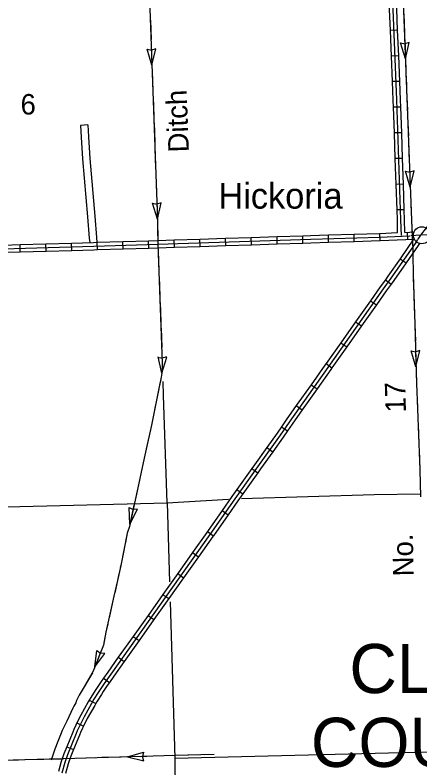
# Model space of a CAD drawing. Extents: x -5566 to 1759129, y -3726 to 731467.
# Drawn here: x -4880.9 to -4817.8, y 389.7 to 507.2 of the extents above; entities that cross this region are included whole.
import ezdxf

# ---------------------------------------------------------------- set-up
doc = ezdxf.new("R2010")
doc.units = 0
doc.layers.add('Default', color=7, linetype='Continuous')

msp = doc.modelspace()

# ---------------------------------------------------------------- linework, layer by layer
at = {"layer": 'Default'}
for p, q in [((-4821.23, 504.86), (-4822.37, 504.81)), ((-4859.56, 499.37), (-4860.33, 501.87)), ((-4860.33, 501.87), (-4859.65, 501.71)), ((-4858.98, 501.91), (-4859.64, 501.71)), ((-4859.56, 499.37), (-4858.98, 501.91)), ((-4820.02, 500.38), (-4820.79, 502.87)), ((-4820.79, 502.87), (-4820.11, 502.72)), ((-4819.44, 502.92), (-4820.1, 502.72)), ((-4820.02, 500.38), (-4819.44, 502.92)), ((-4821.06, 500.85), (-4822.2, 500.8)), ((-4820.9, 496.85), (-4822.03, 496.8)), ((-4820.74, 492.84), (-4821.88, 492.8)), ((-4820.6, 488.83), (-4821.74, 488.79)), ((-4820.47, 484.82), (-4821.6, 484.78)), ((-4819.26, 480.35), (-4820.03, 482.84)), ((-4820.03, 482.84), (-4819.35, 482.68)), ((-4818.68, 482.89), (-4819.34, 482.68)), ((-4819.26, 480.35), (-4818.68, 482.89)), ((-4820.33, 480.81), (-4821.47, 480.77)), ((-4858.71, 475.33), (-4859.47, 477.82)), ((-4859.47, 477.82), (-4858.79, 477.67)), ((-4858.12, 477.87), (-4858.79, 477.67)), ((-4858.71, 475.33), (-4858.12, 477.87)), ((-4820.19, 476.81), (-4821.33, 476.77)), ((-4844.02, 471.34), (-4844.06, 472.48)), ((-4840.02, 471.48), (-4840.05, 472.61)), ((-4836.01, 471.61), (-4836.05, 472.75)), ((-4832, 471.73), (-4832.04, 472.87)), ((-4827.99, 471.86), (-4828.03, 473)), ((-4823.98, 471.98), (-4824.03, 473.12)), ((-4819.63, 472.16), (-4819.68, 473.3)), ((-4880.1, 470.23), (-4880.13, 471.36)), ((-4876.09, 470.34), (-4876.12, 471.48)), ((-4872.08, 470.46), (-4872.11, 471.6)), ((-4868.07, 470.58), (-4868.11, 471.72)), ((-4864.06, 470.7), (-4864.1, 471.84)), ((-4860.06, 470.82), (-4860.09, 471.96)), ((-4856.05, 470.95), (-4856.08, 472.09)), ((-4852.04, 471.08), (-4852.08, 472.22)), ((-4848.03, 471.21), (-4848.07, 472.35)), ((-4820.86, 469.15), (-4819.92, 468.51)), ((-4823.15, 465.88), (-4822.22, 465.21)), ((-4825.48, 462.61), (-4824.55, 461.95)), ((-4827.79, 459.33), (-4826.86, 458.67)), ((-4830.1, 456.05), (-4829.17, 455.4)), ((-4817.76, 454.83), (-4818.42, 454.63)), ((-4818.37, 452.3), (-4817.76, 454.83)), ((-4858.66, 453.78), (-4857.98, 453.62)), ((-4858.01, 451.29), (-4858.59, 453.83)), ((-4858.01, 451.29), (-4857.24, 453.78)), ((-4857.31, 453.83), (-4857.97, 453.62)), ((-4818.37, 452.3), (-4819.11, 454.8)), ((-4819.11, 454.8), (-4818.43, 454.63)), ((-4832.41, 452.78), (-4831.48, 452.12)), ((-4834.72, 449.5), (-4833.79, 448.84)), ((-4837.04, 446.23), (-4836.11, 445.57)), ((-4839.34, 442.93), (-4838.4, 442.29)), ((-4841.65, 439.67), (-4840.72, 439.01)), ((-4843.98, 436.4), (-4843.05, 435.74)), ((-4846.3, 433.14), (-4845.37, 432.48)), ((-4863, 427.75), (-4863.13, 430.35)), ((-4863.13, 430.35), (-4862.51, 430.04)), ((-4863, 427.75), (-4861.81, 430.07)), ((-4861.81, 430.07), (-4862.5, 430.04)), ((-4848.61, 429.85), (-4847.68, 429.2)), ((-4850.91, 426.57), (-4849.98, 425.91)), ((-4853.23, 423.3), (-4852.3, 422.64)), ((-4855.54, 420.03), (-4854.62, 419.37)), ((-4857.86, 416.76), (-4856.93, 416.1)), ((-4860.18, 413.49), (-4859.25, 412.83)), ((-4862.5, 410.21), (-4861.57, 409.56)), ((-4868.45, 405.43), (-4868.17, 408.02)), ((-4868.17, 408.02), (-4867.61, 407.61)), ((-4868.45, 405.43), (-4866.91, 407.53)), ((-4866.91, 407.53), (-4867.6, 407.6)), ((-4864.82, 406.94), (-4863.89, 406.29)), ((-4867.14, 403.67), (-4866.21, 403.01)), ((-4869.35, 400.24), (-4868.34, 399.71)), ((-4871.26, 396.71), (-4870.25, 396.19)), ((-4872.85, 392.98), (-4871.8, 392.55)), ((-4863.39, 391.4), (-4860.89, 392.14)), ((-4863.39, 391.4), (-4860.85, 390.79)), ((-4860.89, 392.14), (-4861.05, 391.47)), ((-4860.85, 390.79), (-4861.05, 391.46))]:
    msp.add_line(p, q, dxfattribs=at)
for points in [[(-4820.65, 472.78), (-4820.71, 475.23), (-4821.35, 493.95), (-4821.93, 508.07), (-4822.06, 511.53), (-4822.06, 512.62), (-4822.03, 513.56), (-4822, 513.82), (-4821.97, 514.21), (-4821.8, 514.93), (-4821.58, 516.04), (-4821.5, 516.72), (-4821.48, 517.29), (-4821.49, 518.21), (-4822.18, 534.35), (-4822.2, 535.05), (-4822.95, 553.69), (-4823.07, 557.61), (-4823.78, 574.98), (-4824.52, 594.47)], [(-4785.83, 515.93), (-4792.8, 506.87), (-4795.14, 503.86), (-4797.87, 500.25), (-4801.97, 494.91), (-4802.55, 494.18), (-4802.7, 493.91), (-4802.86, 493.61), (-4804.41, 491.37), (-4806.14, 488.91), (-4809.39, 484.4), (-4812.72, 479.57), (-4814.45, 477.18), (-4815.22, 476.03), (-4815.91, 475.13), (-4817.67, 472.82), (-4818.06, 472.22)], [(-4820.46, 512.01), (-4818.96, 472.49), (-4818.91, 471.43), (-4818.86, 470.81), (-4818.87, 469.76), (-4818.83, 466.73), (-4818.54, 458.88), (-4818.31, 449.71), (-4817.77, 436.19), (-4817.67, 431.97)], [(-4859.93, 509.67), (-4858.75, 476.57), (-4858.64, 471.44), (-4857.95, 452.87), (-4857.98, 452), (-4858.03, 451.3), (-4858.12, 450.69), (-4858.43, 449.17), (-4859.31, 444.75), (-4859.64, 443.2), (-4860.67, 438.48), (-4863.09, 427.36), (-4863.41, 426.34)], [(-4822.37, 504.81), (-4822.5, 508.05), (-4822.53, 508.82)], [(-4821.23, 504.86), (-4821.36, 508.1), (-4821.39, 508.86)], [(-4820.29, 507.39), (-4820.17, 504.39)], [(-4859.81, 506.39), (-4859.7, 503.38)], [(-4822.2, 500.8), (-4822.37, 504.81)], [(-4821.06, 500.85), (-4821.23, 504.86)], [(-4820.13, 503.39), (-4820.02, 500.38)], [(-4859.67, 502.38), (-4859.56, 499.37)], [(-4822.03, 496.8), (-4822.2, 500.8)], [(-4820.9, 496.85), (-4821.06, 500.85)], [(-4859.53, 498.37), (-4859.47, 496.87)], [(-4819.98, 499.38), (-4819.93, 497.88)], [(-4819.93, 497.88), (-4819.87, 496.38)], [(-4859.47, 496.87), (-4859.42, 495.37)], [(-4821.88, 492.8), (-4821.92, 493.93), (-4822.03, 496.8)], [(-4820.74, 492.84), (-4820.78, 493.98), (-4820.9, 496.85)], [(-4819.83, 495.37), (-4819.72, 492.37)], [(-4859.38, 494.37), (-4859.28, 491.36)], [(-4821.74, 488.79), (-4821.88, 492.8)], [(-4820.6, 488.83), (-4820.74, 492.84)], [(-4819.68, 491.37), (-4819.56, 488.36)], [(-4859.24, 490.36), (-4859.13, 487.35)], [(-4869.57, 490.05), (-4870.7, 489.98), (-4870.6, 488.11), (-4870.38, 484.73), (-4869.63, 475.69), (-4869.35, 472.38), (-4869.28, 471.68)], [(-4869.57, 490.05), (-4869.46, 488.18), (-4869.24, 484.82), (-4868.49, 475.79), (-4868.21, 472.49), (-4868.14, 471.71)], [(-4821.6, 484.78), (-4821.74, 488.79)], [(-4820.47, 484.82), (-4820.6, 488.83)], [(-4819.53, 487.36), (-4819.41, 484.35)], [(-4859.1, 486.35), (-4858.99, 483.35)], [(-4821.47, 480.77), (-4821.6, 484.78)], [(-4820.33, 480.81), (-4820.47, 484.82)], [(-4819.37, 483.35), (-4819.26, 480.35)], [(-4858.96, 482.34), (-4858.85, 479.34)], [(-4821.33, 476.77), (-4821.47, 480.77)], [(-4820.19, 476.81), (-4820.33, 480.81)], [(-4858.81, 478.34), (-4858.75, 476.57), (-4858.72, 475.33)], [(-4819.22, 479.35), (-4819.11, 476.34)], [(-4821.23, 473.24), (-4821.28, 475.21), (-4821.33, 476.77)], [(-4820.09, 473.28), (-4820.14, 475.24), (-4820.19, 476.81)], [(-4760.09, 474.99), (-4769.7, 474.49), (-4779.76, 474.01), (-4783.25, 473.89), (-4795.37, 473.47), (-4799.28, 473.39), (-4811.13, 473.04), (-4817.67, 472.82), (-4819.19, 472.75)], [(-4819.07, 475.34), (-4819.01, 473.84)], [(-4858.7, 474.33), (-4858.67, 472.82)], [(-4819.01, 473.84), (-4818.99, 473.33)], [(-4858.67, 472.82), (-4858.65, 472.01)], [(-4858.64, 471.44), (-4834.8, 472.22), (-4824.02, 472.55), (-4819.38, 472.74), (-4819.33, 472.75)], [(-4848.07, 472.35), (-4844.06, 472.48)], [(-4844.06, 472.48), (-4840.05, 472.61)], [(-4840.05, 472.61), (-4836.05, 472.75)], [(-4836.05, 472.75), (-4834.82, 472.79), (-4832.04, 472.87)], [(-4832.04, 472.87), (-4828.03, 473)], [(-4828.03, 473), (-4824.04, 473.12), (-4824.03, 473.12)], [(-4824.03, 473.12), (-4821.23, 473.24)], [(-4820.09, 473.28), (-4818.68, 473.34)], [(-4888.25, 470.56), (-4868.65, 471.13), (-4858.64, 471.44)], [(-4884.14, 471.25), (-4880.13, 471.36)], [(-4880.13, 471.36), (-4876.12, 471.48)], [(-4876.12, 471.48), (-4872.11, 471.6)], [(-4872.11, 471.6), (-4868.67, 471.7), (-4868.11, 471.72)], [(-4868.11, 471.72), (-4864.1, 471.84)], [(-4864.1, 471.84), (-4860.09, 471.96)], [(-4860.09, 471.96), (-4858.66, 472.01), (-4856.08, 472.09)], [(-4856.08, 472.09), (-4852.08, 472.22)], [(-4852.08, 472.22), (-4848.07, 472.35)], [(-4818.12, 472.14), (-4818.49, 471.56), (-4822.28, 466.1), (-4823.47, 464.46), (-4832.12, 452.2), (-4838.15, 443.66), (-4839.55, 441.63), (-4843.08, 436.68), (-4846.62, 431.7), (-4850.54, 426.11)], [(-4848.03, 471.21), (-4844.02, 471.34)], [(-4844.02, 471.34), (-4840.02, 471.48)], [(-4840.02, 471.48), (-4836.01, 471.61)], [(-4836.01, 471.61), (-4834.78, 471.65), (-4832, 471.73)], [(-4832, 471.73), (-4827.99, 471.86)], [(-4827.99, 471.86), (-4824, 471.98), (-4823.98, 471.98)], [(-4823.98, 471.98), (-4819.97, 472.15)], [(-4818.74, 472.2), (-4820.86, 469.15)], [(-4819.97, 472.15), (-4818.74, 472.2)], [(-4817.82, 471.55), (-4818.02, 471.24), (-4819.92, 468.51)], [(-4884.1, 470.11), (-4880.1, 470.23)], [(-4880.1, 470.23), (-4876.09, 470.34)], [(-4876.09, 470.34), (-4872.08, 470.46)], [(-4872.08, 470.46), (-4868.63, 470.56), (-4868.07, 470.58)], [(-4868.07, 470.58), (-4864.06, 470.7)], [(-4864.06, 470.7), (-4860.06, 470.82)], [(-4860.06, 470.82), (-4858.62, 470.87), (-4856.05, 470.95)], [(-4858.6, 470.32), (-4858.48, 467.31)], [(-4856.05, 470.95), (-4852.04, 471.08)], [(-4852.04, 471.08), (-4848.03, 471.21)], [(-4820.86, 469.15), (-4822.74, 466.43), (-4823.15, 465.88)], [(-4818.87, 470.02), (-4818.85, 468.33)], [(-4819.92, 468.51), (-4821.81, 465.77), (-4822.22, 465.21)], [(-4818.83, 467.33), (-4818.83, 466.73), (-4818.74, 464.32)], [(-4858.45, 466.31), (-4858.34, 463.31)], [(-4823.15, 465.88), (-4823.94, 464.79), (-4825.48, 462.61)], [(-4822.22, 465.21), (-4823.01, 464.13), (-4824.55, 461.95)], [(-4818.7, 463.32), (-4818.59, 460.31)], [(-4858.3, 462.31), (-4858.19, 459.3)], [(-4825.48, 462.61), (-4827.79, 459.33)], [(-4824.55, 461.95), (-4826.86, 458.67)], [(-4827.79, 459.33), (-4830.1, 456.05)], [(-4826.86, 458.67), (-4829.17, 455.4)], [(-4818.55, 459.31), (-4818.54, 458.88), (-4818.47, 456.31)], [(-4858.15, 458.3), (-4858.04, 455.29)], [(-4830.1, 456.05), (-4832.41, 452.78)], [(-4829.17, 455.4), (-4831.48, 452.12)], [(-4818.45, 455.3), (-4818.37, 452.3)], [(-4858, 454.29), (-4857.95, 452.87), (-4857.98, 452), (-4858.03, 451.3), (-4858.03, 451.29)], [(-4832.41, 452.78), (-4832.58, 452.53), (-4834.72, 449.5)], [(-4831.48, 452.12), (-4831.65, 451.87), (-4833.79, 448.84)], [(-4818.35, 451.29), (-4818.31, 449.79)], [(-4858.2, 450.3), (-4858.43, 449.17), (-4858.5, 448.83)], [(-4857.17, 431.08), (-4857.77, 447.81), (-4857.83, 450.01)], [(-4834.72, 449.5), (-4837.04, 446.23)], [(-4818.31, 449.79), (-4818.31, 449.71), (-4818.25, 448.29)], [(-4858.5, 448.83), (-4858.79, 447.35)], [(-4833.79, 448.84), (-4836.11, 445.57)], [(-4818.21, 447.29), (-4818.09, 444.28)], [(-4858.99, 446.37), (-4859.31, 444.75), (-4859.6, 443.42)], [(-4837.04, 446.23), (-4838.62, 443.99), (-4839.34, 442.93)], [(-4836.11, 445.57), (-4837.68, 443.34), (-4838.4, 442.29)], [(-4818.05, 443.28), (-4817.93, 440.28)], [(-4859.81, 442.44), (-4860.45, 439.51)], [(-4839.34, 442.93), (-4840.01, 441.95), (-4841.65, 439.67)], [(-4838.4, 442.29), (-4839.08, 441.3), (-4840.72, 439.01)], [(-4841.65, 439.67), (-4843.55, 437.01), (-4843.98, 436.4)], [(-4860.66, 438.53), (-4860.67, 438.48), (-4861.3, 435.59)], [(-4840.72, 439.01), (-4842.62, 436.35), (-4843.05, 435.74)], [(-4817.9, 439.27), (-4817.78, 436.27)], [(-4843.98, 436.4), (-4846.3, 433.14)], [(-4843.05, 435.74), (-4845.37, 432.48)], [(-4861.51, 434.61), (-4862.15, 431.67)], [(-4846.3, 433.14), (-4847.09, 432.03), (-4848.61, 429.85)], [(-4857.17, 431.08), (-4847.64, 431.64)], [(-4845.37, 432.48), (-4846.16, 431.37), (-4847.68, 429.2)], [(-4845.6, 431.74), (-4824.91, 432.35), (-4817.69, 432.44)], [(-4896.92, 430.07), (-4857.17, 431.08)], [(-4862.37, 430.69), (-4863, 427.75)], [(-4857.17, 431.08), (-4856.81, 418.73)], [(-4848.61, 429.85), (-4850.91, 426.57)], [(-4847.68, 429.2), (-4849.98, 425.91)], [(-4863.27, 426.79), (-4863.41, 426.34)], [(-4850.54, 426.11), (-4865.99, 404.31), (-4867.01, 402.87), (-4867.65, 401.93), (-4867.95, 401.46), (-4868.63, 400.39), (-4868.99, 399.71), (-4870.16, 397.64), (-4870.93, 396.11), (-4871.22, 395.45), (-4871.41, 395.03), (-4872.75, 391.71), (-4873.16, 390.5), (-4873.64, 388.88)], [(-4863.41, 426.34), (-4864.44, 421.29), (-4864.93, 418.93), (-4865.5, 416.49), (-4866.74, 410.88), (-4867.14, 408.82), (-4868.71, 404.77)], [(-4863.41, 426.34), (-4863.71, 424.86)], [(-4850.91, 426.57), (-4851, 426.43), (-4853.23, 423.3)], [(-4849.98, 425.91), (-4850.07, 425.78), (-4852.3, 422.64)], [(-4863.91, 423.88), (-4864.44, 421.29), (-4864.51, 420.94)], [(-4853.23, 423.3), (-4855.54, 420.03)], [(-4852.3, 422.64), (-4854.62, 419.37)], [(-4864.72, 419.95), (-4864.93, 418.93), (-4865.38, 417.02)], [(-4855.54, 420.03), (-4857.86, 416.76)], [(-4854.62, 419.37), (-4856.93, 416.1)], [(-4865.6, 416.04), (-4866.25, 413.11)], [(-4857.86, 416.76), (-4860.18, 413.49)], [(-4856.93, 416.1), (-4859.25, 412.83)], [(-4856.72, 415.58), (-4855.99, 391.19)], [(-4860.18, 413.49), (-4862.5, 410.21)], [(-4859.25, 412.83), (-4861.57, 409.56)], [(-4866.46, 412.13), (-4866.74, 410.88), (-4867.07, 409.18)], [(-4862.5, 410.21), (-4864.82, 406.94)], [(-4861.57, 409.56), (-4863.89, 406.29)], [(-4867.37, 408.23), (-4868.45, 405.43)], [(-4864.82, 406.94), (-4866.46, 404.64), (-4867.14, 403.67)], [(-4863.89, 406.29), (-4865.53, 403.98), (-4866.21, 403.01)], [(-4868.71, 404.77), (-4870.14, 402.32), (-4870.93, 401.05), (-4871.33, 400.18), (-4871.43, 399.85), (-4871.57, 399.59), (-4871.74, 399.31), (-4871.91, 399), (-4872.85, 397), (-4873.55, 395.5), (-4874.72, 392.6), (-4875.2, 391.19), (-4875.35, 390.94)], [(-4868.86, 404.51), (-4869.62, 403.21)], [(-4869.62, 403.21), (-4870.14, 402.32), (-4870.39, 401.92)], [(-4867.14, 403.67), (-4867.48, 403.19), (-4868.12, 402.24), (-4868.43, 401.76), (-4869.12, 400.68), (-4869.35, 400.24)], [(-4866.21, 403.01), (-4866.55, 402.54), (-4867.17, 401.62), (-4867.46, 401.15), (-4868.13, 400.11), (-4868.34, 399.71)], [(-4870.92, 401.07), (-4870.93, 401.05), (-4871.33, 400.18), (-4871.43, 399.85), (-4871.57, 399.59), (-4871.74, 399.31), (-4871.91, 399), (-4872.21, 398.36)], [(-4869.35, 400.24), (-4869.49, 399.98), (-4870.66, 397.9), (-4871.26, 396.71)], [(-4868.34, 399.71), (-4868.49, 399.44), (-4869.65, 397.37), (-4870.25, 396.19)], [(-4872.63, 397.45), (-4872.85, 397), (-4873.55, 395.5), (-4873.87, 394.71)], [(-4871.26, 396.71), (-4871.44, 396.35), (-4871.74, 395.68), (-4871.93, 395.25), (-4872.85, 392.98)], [(-4870.25, 396.19), (-4870.41, 395.86), (-4870.7, 395.22), (-4870.89, 394.8), (-4871.8, 392.55)], [(-4874.24, 393.78), (-4874.72, 392.6), (-4875.26, 391.03)], [(-4872.85, 392.98), (-4873.29, 391.9), (-4873.71, 390.67), (-4874.16, 389.13)], [(-4871.8, 392.55), (-4872.22, 391.51), (-4872.62, 390.32), (-4873.07, 388.81)], [(-4849.86, 391.75), (-4856.04, 391.63), (-4857.65, 391.56), (-4873.29, 391.1), (-4873.39, 391.11), (-4873.78, 391.05), (-4874.32, 391.06), (-4875.59, 391.02), (-4881.24, 390.88), (-4895.61, 390.55)], [(-4864.39, 391.37), (-4867.39, 391.28)], [(-4860.38, 391.48), (-4863.39, 391.4)], [(-4856.37, 391.62), (-4857.65, 391.56), (-4859.38, 391.51)], [(-4855.99, 391.19), (-4816.43, 392.17)], [(-4852.36, 391.7), (-4855.37, 391.64)], [(-4849.86, 391.75), (-4851.36, 391.72)], [(-4880.41, 390.9), (-4881.24, 390.88), (-4883.42, 390.83)], [(-4876.41, 391), (-4879.41, 390.93)], [(-4873.9, 391.05), (-4874.32, 391.06), (-4875.4, 391.02)], [(-4873.57, 391.08), (-4873.78, 391.05), (-4873.9, 391.05)], [(-4868.4, 391.25), (-4871.4, 391.16)], [(-4855.99, 391.19), (-4855.86, 375.67), (-4855.94, 371.24)]]:
    msp.add_lwpolyline(points, dxfattribs=at)
msp.add_circle((-4817.45, 472.82), 1.33, dxfattribs=at)

# ---------------------------------------------------------------- texts
for s, height, p in [('6', 3.2, (-4880.06, 491.67)), ('Hickoria', 4.01, (-4849.2, 476.98)), ('CLAY', 7.676, (-4828.76, 401.35)), ('COUNTY', 7.676, (-4834.77, 389.83))]:
    msp.add_text(s, height=height, dxfattribs=at).set_placement(p)
for s, rotation, p in [('Ditch', 92.1682, (-4853.79, 485.82)), ('17', 91.3544, (-4819.93, 445.18)), ('No.', 91.3544, (-4818.72, 419.62))]:
    msp.add_text(s, height=3.205, rotation=rotation, dxfattribs=at).set_placement(p)

doc.saveas('drawing.dxf')
